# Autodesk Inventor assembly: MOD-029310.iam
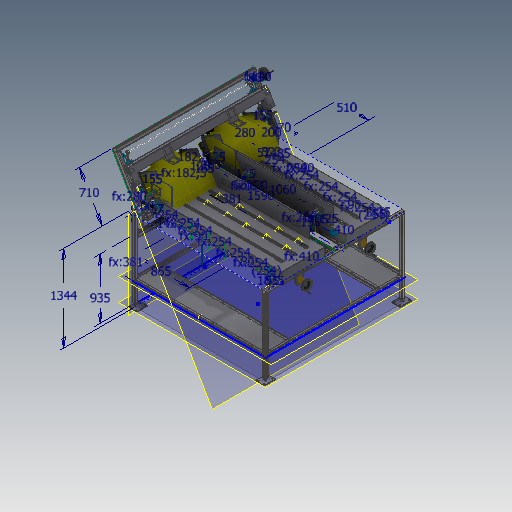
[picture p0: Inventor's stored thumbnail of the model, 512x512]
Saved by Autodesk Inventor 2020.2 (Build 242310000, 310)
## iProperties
Created: 2019-10
Part Number: MOD-029310.iam
Document SubType Name: Assembly
Designer: lutzd
Mass: 576257 g
Surface Area: 445992 cm^2
Volume: 104131 cm^3
Density: 5.53397 g/cm^3
VLDS_Profile: Default Assembly
VLDS_TimeStamp: 2016-07-29
VLDS_FailCnt: 0
VLDS_AcceptCnt: 0
Dimensions: 2423,5x1993,9x2729,7 mm
Mass: 576,257 kg
DocNumber: MOD-029310.iam
Folder: 01 - Themengebiete\Simplification\01 - Packaging machine\.\
VDS_Category: 3D Komponenten
VDS_NumSchm: Kein
Title: MOD-029310
Author: lutzd
Revision Number: -
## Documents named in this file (17)
- D:\07 - DEMODATEN\OTX 2019 - Dataset - UPDATE - Dez2019\Designs\07-Packing machine\MOD-029310.iam
- D:\07 - DEMODATEN\OTX 2019 - Dataset - UPDATE - Dez2019\Designs\07-Packing machine\500586R.iam
- D:\07 - DEMODATEN\OTX 2019 - Dataset - UPDATE - Dez2019\Designs\07-Packing machine\Parts\ADSK-011671.ipt
- D:\07 - DEMODATEN\OTX 2019 - Dataset - UPDATE - Dez2019\Designs\07-Packing machine\ADSK-014389.iam
- D:\07 - DEMODATEN\OTX 2019 - Dataset - UPDATE - Dez2019\Content Center Files\de-DE\DIN 125-1  B\DIN 125-1 - B 8,4.ipt
- D:\07 - DEMODATEN\OTX 2019 - Dataset - UPDATE - Dez2019\Content Center Files\de-DE\ISO 4762(2)\ISO 4762 - M8 x 25ISO.ipt
- D:\07 - DEMODATEN\OTX 2019 - Dataset - UPDATE - Dez2019\Designs\07-Packing machine\SUB-229310.iam
- D:\07 - DEMODATEN\OTX 2019 - Dataset - UPDATE - Dez2019\Content Center Files\de-DE\ISO 4762(2)\ISO 4762 - M8 x 16ISO.ipt
- D:\07 - DEMODATEN\OTX 2019 - Dataset - UPDATE - Dez2019\Designs\07-Packing machine\SUB-239310.iam
- D:\07 - DEMODATEN\OTX 2019 - Dataset - UPDATE - Dez2019\Designs\07-Packing machine\SUB-279310.iam
- D:\07 - DEMODATEN\OTX 2019 - Dataset - UPDATE - Dez2019\Content Center Files\de-DE\ISO 4762(2)\ISO 4762 - M8 x 20ISO.ipt
- D:\07 - DEMODATEN\OTX 2019 - Dataset - UPDATE - Dez2019\Designs\07-Packing machine\SUB-299310.iam
- D:\07 - DEMODATEN\OTX 2019 - Dataset - UPDATE - Dez2019\Designs\07-Packing machine\SUB-269310.iam
- D:\07 - DEMODATEN\OTX 2019 - Dataset - UPDATE - Dez2019\Designs\07-Packing machine\500652R.iam
- D:\07 - DEMODATEN\OTX 2019 - Dataset - UPDATE - Dez2019\Designs\07-Packing machine\500652L.iam
- D:\07 - DEMODATEN\OTX 2019 - Dataset - UPDATE - Dez2019\Designs\07-Packing machine\SUB-259310.iam
- D:\07 - DEMODATEN\OTX 2019 - Dataset - UPDATE - Dez2019\Designs\07-Packing machine\Parts\ADSK-014502.ipt
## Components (534 placed, 16 different names)
1. 500586R:1 [sub-assembly] — Passend:49, Fluchtend:4, Passend:58, Passend:59, Fluchtend:5, Fluchtend:6, Fluchtend:7, Passend:60, Passend:141, Passend:143, Fluchtend:8, Fluchtend:9, Passend:161, Passend:174, Fluchtend:10, Passend:272, Passend:289, Passend:290, Passend:295, Fluchtend:293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
2. ADSK-011671:1
3. ADSK-011671:2
4. ADSK-014389:1 [sub-assembly] — Passend:48, Passend:49, Fluchtend:4, Passend:51, Passend:53, Passend:55, Passend:57, Passend:391, Fluchtend:393
5. SUB-229310:1 [sub-assembly] — Passend:58, Fluchtend:5, Fluchtend:7, Passend:145, Passend:147, Passend:149, Passend:151
6. SUB-229310:2 [sub-assembly] — Passend:59, Fluchtend:6, Passend:60, Passend:62, Passend:64, Passend:66, Passend:68, Passend:70, Passend:72, Passend:74, Passend:76, Passend:78, Passend:80, Passend:82, Passend:84, Passend:86, Passend:88, Passend:90, Passend:92, Passend:110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
7. SUB-239310:1 [sub-assembly] — Passend:141, Passend:143, Fluchtend:8, Passend:169, Passend:171, Passend:173, Passend:176, Passend:178, Passend:180, Passend:182, Passend:184, Passend:186, Passend:188, Passend:190, Passend:240, Passend:242, Passend:260, Passend:262, Fluchtend:298, Passend:385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
8. SUB-279310:1 [sub-assembly] — Fluchtend:9, Passend:161, Passend:163, Passend:165, Passend:167, Passend:174, Passend:192, Passend:194, Passend:196, Passend:198, Passend:200, Passend:202, Passend:204, Passend:206, Passend:244, Passend:246, Passend:256, Passend:258, Passend:271, Fluchtend:389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
9. SUB-299310:1 [sub-assembly] — Passend:271, Fluchtend:10, Passend:272, Passend:274, Passend:276, Passend:278, Passend:280, Passend:282, Passend:284
10. SUB-269310:1 [sub-assembly] — Passend:289, Fluchtend:292, Passend:290, Passend:292, Passend:294, Passend:296, Passend:299
11. 500652R:1 [sub-assembly] — Passend:295, Fluchtend:293, Passend:296, Fluchtend:390
12. 500652L:1 [sub-assembly] — Passend:297, Passend:298, Passend:299, Fluchtend:299
13. SUB-259310:1 [sub-assembly] — Fluchtend:294, Passend:390, Fluchtend:295, Fluchtend:391, Passend:301, Passend:303, Passend:305, Passend:307, Passend:309, Passend:311, Passend:313, Passend:315, Passend:317, Passend:319, Passend:321, Passend:323, Passend:325, Passend:327, Passend:329, Passend:331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
14. ADSK-014502:307 — Fluchtend:392, Passend:391, Fluchtend:393
15. DIN 125-1 B B 8,4:85 — Passend:377, Passend:379
16. DIN 125-1 B B 8,4:86
17. DIN 125-1 B B 8,4:87
18. DIN 125-1 B B 8,4:88
19. DIN 125-1 B B 8,4:89 — Passend:301, Passend:361, Passend:363, Passend:365, Passend:367
20. DIN 125-1 B B 8,4:90 — Passend:303
21. DIN 125-1 B B 8,4:91 — Passend:305
22. DIN 125-1 B B 8,4:92 — Passend:307
23. DIN 125-1 B B 8,4:93 — Passend:309, Passend:369, Passend:371, Passend:373, Passend:375
24. DIN 125-1 B B 8,4:94 — Passend:311
25. DIN 125-1 B B 8,4:95 — Passend:313
26. DIN 125-1 B B 8,4:96 — Passend:315
27. DIN 125-1 B B 8,4:97
28. DIN 125-1 B B 8,4:98
29. DIN 125-1 B B 8,4:99 — Passend:317
30. DIN 125-1 B B 8,4:100 — Passend:319, Passend:353, Passend:355, Passend:357, Passend:359
31. DIN 125-1 B B 8,4:101 — Passend:321
32. DIN 125-1 B B 8,4:102 — Passend:323
33. DIN 125-1 B B 8,4:103 — Passend:325
34. DIN 125-1 B B 8,4:104 — Passend:327
35. DIN 125-1 B B 8,4:105 — Passend:329
36. DIN 125-1 B B 8,4:106 — Passend:331
37. DIN 125-1 B B 8,4:107 — Passend:333
38. DIN 125-1 B B 8,4:108 — Passend:335
39. DIN 125-1 B B 8,4:109 — Passend:337
40. DIN 125-1 B B 8,4:110 — Passend:339, Passend:341, Passend:343, Passend:345, Passend:351
41. ISO 4762 M8 x 20:11 — Passend:341
42. ISO 4762 M8 x 20:12 — Passend:343
43. ISO 4762 M8 x 20:13 — Passend:345
44. ISO 4762 M8 x 20:16 — Passend:351
45. ISO 4762 M8 x 25:29
46. ISO 4762 M8 x 25:30
47. ISO 4762 M8 x 20:17 — Passend:353
48. ISO 4762 M8 x 20:18 — Passend:355
49. ISO 4762 M8 x 20:19 — Passend:357
50. ISO 4762 M8 x 20:20 — Passend:359
51. ISO 4762 M8 x 25:31
52. ISO 4762 M8 x 25:32
53. ISO 4762 M8 x 20:21 — Passend:361
54. ISO 4762 M8 x 20:22 — Passend:363
55. ISO 4762 M8 x 20:23 — Passend:365
56. ISO 4762 M8 x 20:24 — Passend:367
57. ISO 4762 M8 x 16:51 — Passend:369
58. ISO 4762 M8 x 16:52 — Passend:371
59. ISO 4762 M8 x 16:53 — Passend:373
60. ISO 4762 M8 x 16:54 — Passend:375
61. ISO 4762 M8 x 16:55 — Passend:377
62. ISO 4762 M8 x 16:56 — Passend:379
63. DIN 125-1 B B 8,4:69
64. DIN 125-1 B B 8,4:70
65. DIN 125-1 B B 8,4:71
66. DIN 125-1 B B 8,4:72
67. DIN 125-1 B B 8,4:73
68. DIN 125-1 B B 8,4:74
69. DIN 125-1 B B 8,4:75 — Passend:292
70. DIN 125-1 B B 8,4:76 — Passend:294
71. DIN 125-1 B B 8,4:77
72. DIN 125-1 B B 8,4:78
73. DIN 125-1 B B 8,4:79
74. DIN 125-1 B B 8,4:80
75. DIN 125-1 B B 8,4:81
76. DIN 125-1 B B 8,4:82
77. DIN 125-1 B B 8,4:83
78. DIN 125-1 B B 8,4:84
79. ISO 4762 M8 x 25:13
80. ISO 4762 M8 x 25:14
81. ISO 4762 M8 x 25:15
82. ISO 4762 M8 x 25:16
83. ISO 4762 M8 x 25:17
84. ISO 4762 M8 x 25:18
85. ISO 4762 M8 x 25:19
86. ISO 4762 M8 x 25:20
87. ISO 4762 M8 x 25:21
88. ISO 4762 M8 x 25:22
89. ISO 4762 M8 x 25:23
90. ISO 4762 M8 x 25:24
91. ISO 4762 M8 x 25:25
92. ISO 4762 M8 x 25:26
93. ISO 4762 M8 x 25:27
94. ISO 4762 M8 x 25:28
95. DIN 125-1 B B 8,4:63 — Passend:274
96. DIN 125-1 B B 8,4:64 — Passend:276
97. DIN 125-1 B B 8,4:65 — Passend:278
98. DIN 125-1 B B 8,4:66 — Passend:280
99. DIN 125-1 B B 8,4:67 — Passend:282, Passend:286, Passend:288
100. DIN 125-1 B B 8,4:68 — Passend:284
101. ISO 4762 M8 x 20:5 — Passend:286
102. ISO 4762 M8 x 20:6 — Passend:288
103. ISO 4762 M8 x 20:7
104. ISO 4762 M8 x 20:8
105. ISO 4762 M8 x 20:9
106. ISO 4762 M8 x 20:10
107. DIN 125-1 B B 8,4:59 — Passend:256
108. DIN 125-1 B B 8,4:60 — Passend:258, Passend:268, Passend:270
109. DIN 125-1 B B 8,4:61 — Passend:260, Passend:264, Passend:266
110. DIN 125-1 B B 8,4:62 — Passend:262
111. ISO 4762 M8 x 16:47 — Passend:264
112. ISO 4762 M8 x 16:48 — Passend:266
113. ISO 4762 M8 x 16:49 — Passend:268
114. ISO 4762 M8 x 16:50 — Passend:270
115. DIN 125-1 B B 8,4:55 — Passend:240
116. DIN 125-1 B B 8,4:56 — Passend:242, Passend:252, Passend:254
117. DIN 125-1 B B 8,4:57 — Passend:244, Passend:248, Passend:250
118. DIN 125-1 B B 8,4:58 — Passend:246
119. ISO 4762 M8 x 20:1 — Passend:248
120. ISO 4762 M8 x 20:2 — Passend:250
121. ISO 4762 M8 x 20:3 — Passend:252
122. ISO 4762 M8 x 20:4 — Passend:254
123. DIN 125-1 B B 8,4:33 — Passend:163
124. DIN 125-1 B B 8,4:34 — Passend:165
125. DIN 125-1 B B 8,4:35 — Passend:167
126. DIN 125-1 B B 8,4:36 — Passend:169
127. DIN 125-1 B B 8,4:37 — Passend:171
128. DIN 125-1 B B 8,4:38 — Passend:173
129. ISO 4762 M8 x 16:25
130. ISO 4762 M8 x 16:26
131. ISO 4762 M8 x 16:27
132. ISO 4762 M8 x 16:28
133. ISO 4762 M8 x 16:29
134. ISO 4762 M8 x 16:30
135. DIN 125-1 B B 8,4:39 — Passend:176
136. DIN 125-1 B B 8,4:40 — Passend:178
137. DIN 125-1 B B 8,4:41 — Passend:180
138. DIN 125-1 B B 8,4:42 — Passend:182
139. DIN 125-1 B B 8,4:43 — Passend:184, Passend:208, Passend:210, Passend:212, Passend:214, Passend:216, Passend:218, Passend:220, Passend:222
140. DIN 125-1 B B 8,4:44 — Passend:186
141. DIN 125-1 B B 8,4:45 — Passend:188
142. DIN 125-1 B B 8,4:46 — Passend:190
143. DIN 125-1 B B 8,4:47 — Passend:192, Passend:224, Passend:226, Passend:228, Passend:230, Passend:232, Passend:234, Passend:236, Passend:238
144. DIN 125-1 B B 8,4:48 — Passend:194
145. DIN 125-1 B B 8,4:49 — Passend:196
146. DIN 125-1 B B 8,4:50 — Passend:198
147. DIN 125-1 B B 8,4:51 — Passend:200
148. DIN 125-1 B B 8,4:52 — Passend:202
149. DIN 125-1 B B 8,4:53 — Passend:204
150. DIN 125-1 B B 8,4:54 — Passend:206
151. ISO 4762 M8 x 16:31 — Passend:208
152. ISO 4762 M8 x 16:32 — Passend:210
153. ISO 4762 M8 x 16:33 — Passend:212
154. ISO 4762 M8 x 16:34 — Passend:214
155. ISO 4762 M8 x 16:35 — Passend:216
156. ISO 4762 M8 x 16:36 — Passend:218
157. ISO 4762 M8 x 16:37 — Passend:220
158. ISO 4762 M8 x 16:38 — Passend:222
159. ISO 4762 M8 x 16:39 — Passend:224
160. ISO 4762 M8 x 16:40 — Passend:226
161. ISO 4762 M8 x 16:41 — Passend:228
162. ISO 4762 M8 x 16:42 — Passend:230
163. ISO 4762 M8 x 16:43 — Passend:232
164. ISO 4762 M8 x 16:44 — Passend:234
165. ISO 4762 M8 x 16:45 — Passend:236
166. ISO 4762 M8 x 16:46 — Passend:238
167. DIN 125-1 B B 8,4:29 — Passend:145, Passend:153, Passend:155, Passend:157, Passend:159
168. DIN 125-1 B B 8,4:30 — Passend:147
169. DIN 125-1 B B 8,4:31 — Passend:149
170. DIN 125-1 B B 8,4:32 — Passend:151
171. ISO 4762 M8 x 16:21 — Passend:153
172. ISO 4762 M8 x 16:22 — Passend:155
173. ISO 4762 M8 x 16:23 — Passend:157
174. ISO 4762 M8 x 16:24 — Passend:159
175. ISO 4762 M8 x 16:17 — Passend:134
176. ISO 4762 M8 x 16:18 — Passend:136
177. ISO 4762 M8 x 16:19 — Passend:138
178. ISO 4762 M8 x 16:20 — Passend:140
179. ISO 4762 M8 x 16:6 — Passend:112
180. ISO 4762 M8 x 16:7 — Passend:114
181. ISO 4762 M8 x 16:8 — Passend:116
182. ISO 4762 M8 x 16:9 — Passend:118
183. ISO 4762 M8 x 16:10 — Passend:120
184. ISO 4762 M8 x 16:11 — Passend:122
185. ISO 4762 M8 x 16:12 — Passend:124
186. ISO 4762 M8 x 16:13 — Passend:126
187. ISO 4762 M8 x 16:14 — Passend:128
188. ISO 4762 M8 x 16:15 — Passend:130
189. ISO 4762 M8 x 16:16 — Passend:132
190. DIN 125-1 B B 8,4:20 — Passend:76
191. DIN 125-1 B B 8,4:21 — Passend:78
192. DIN 125-1 B B 8,4:22 — Passend:80
193. DIN 125-1 B B 8,4:23 — Passend:82
194. DIN 125-1 B B 8,4:24 — Passend:84
195. DIN 125-1 B B 8,4:25 — Passend:86
196. DIN 125-1 B B 8,4:26 — Passend:88
197. DIN 125-1 B B 8,4:27 — Passend:90
198. DIN 125-1 B B 8,4:28 — Passend:92
199. ISO 4762 M8 x 16:5 — Passend:110
200. DIN 125-1 B B 8,4:13 — Passend:62
201. DIN 125-1 B B 8,4:14 — Passend:64
202. DIN 125-1 B B 8,4:15 — Passend:66
203. DIN 125-1 B B 8,4:16 — Passend:68
204. DIN 125-1 B B 8,4:17 — Passend:70
205. DIN 125-1 B B 8,4:18 — Passend:72
206. DIN 125-1 B B 8,4:19 — Passend:74
207. DIN 125-1 B B 8,4:1 — Passend:51
208. DIN 125-1 B B 8,4:2 — Passend:53
209. DIN 125-1 B B 8,4:3 — Passend:55
210. DIN 125-1 B B 8,4:4 — Passend:57
211. DIN 125-1 B B 8,4:5
212. DIN 125-1 B B 8,4:6
213. DIN 125-1 B B 8,4:7
214. DIN 125-1 B B 8,4:8
215. DIN 125-1 B B 8,4:9
216. DIN 125-1 B B 8,4:10
217. DIN 125-1 B B 8,4:11
218. DIN 125-1 B B 8,4:12
219. ISO 4762 M8 x 25:1
220. ISO 4762 M8 x 25:2
221. ISO 4762 M8 x 25:3
222. ISO 4762 M8 x 25:4
223. ISO 4762 M8 x 25:5
224. ISO 4762 M8 x 25:6
225. ISO 4762 M8 x 25:7
226. ISO 4762 M8 x 25:8
227. ISO 4762 M8 x 25:9
228. ISO 4762 M8 x 25:10
229. ISO 4762 M8 x 25:11
230. ISO 4762 M8 x 25:12
231. ADSK-014502:1 [sub-assembly] — Fluchtend:389, Passend:381, Fluchtend:390
232. ADSK-014502:153 [sub-assembly] — Fluchtend:298, Fluchtend:299, Passend:385
233. ADSK-014502:305
234. ADSK-014502:306
235. ADSK-014502:3 [sub-assembly]
236. ADSK-014502:155 [sub-assembly]
237. ADSK-014502:4 [sub-assembly]
238. ADSK-014502:156 [sub-assembly]
239. ADSK-014502:5 [sub-assembly]
240. ADSK-014502:157 [sub-assembly]
241. ADSK-014502:6 [sub-assembly]
242. ADSK-014502:158 [sub-assembly]
243. ADSK-014502:7 [sub-assembly]
244. ADSK-014502:159 [sub-assembly]
245. ADSK-014502:8 [sub-assembly]
246. ADSK-014502:160 [sub-assembly]
247. ADSK-014502:9 [sub-assembly]
248. ADSK-014502:161 [sub-assembly]
249. ADSK-014502:10 [sub-assembly]
250. ADSK-014502:162 [sub-assembly]
251. ADSK-014502:11 [sub-assembly]
252. ADSK-014502:163 [sub-assembly]
253. ADSK-014502:12 [sub-assembly]
254. ADSK-014502:164 [sub-assembly]
255. ADSK-014502:13 [sub-assembly]
256. ADSK-014502:165 [sub-assembly]
257. ADSK-014502:14 [sub-assembly]
258. ADSK-014502:166 [sub-assembly]
259. ADSK-014502:15 [sub-assembly]
260. ADSK-014502:167 [sub-assembly]
261. ADSK-014502:16 [sub-assembly]
262. ADSK-014502:168 [sub-assembly]
263. ADSK-014502:17 [sub-assembly]
264. ADSK-014502:169 [sub-assembly]
265. ADSK-014502:18 [sub-assembly]
266. ADSK-014502:170 [sub-assembly]
267. ADSK-014502:19 [sub-assembly]
268. ADSK-014502:171 [sub-assembly]
269. ADSK-014502:20 [sub-assembly]
270. ADSK-014502:172 [sub-assembly]
271. ADSK-014502:21 [sub-assembly]
272. ADSK-014502:173 [sub-assembly]
273. ADSK-014502:22 [sub-assembly]
274. ADSK-014502:174 [sub-assembly]
275. ADSK-014502:23 [sub-assembly]
276. ADSK-014502:175 [sub-assembly]
277. ADSK-014502:24 [sub-assembly]
278. ADSK-014502:176 [sub-assembly]
279. ADSK-014502:25 [sub-assembly]
280. ADSK-014502:177 [sub-assembly]
281. ADSK-014502:26 [sub-assembly]
282. ADSK-014502:178 [sub-assembly]
283. ADSK-014502:27 [sub-assembly]
284. ADSK-014502:179 [sub-assembly]
285. ADSK-014502:28 [sub-assembly]
286. ADSK-014502:180 [sub-assembly]
287. ADSK-014502:29 [sub-assembly]
288. ADSK-014502:181 [sub-assembly]
289. ADSK-014502:30 [sub-assembly]
290. ADSK-014502:182 [sub-assembly]
291. ADSK-014502:31 [sub-assembly]
292. ADSK-014502:183 [sub-assembly]
293. ADSK-014502:32 [sub-assembly]
294. ADSK-014502:184 [sub-assembly]
295. ADSK-014502:33 [sub-assembly]
296. ADSK-014502:185 [sub-assembly]
297. ADSK-014502:34 [sub-assembly]
298. ADSK-014502:186 [sub-assembly]
299. ADSK-014502:35 [sub-assembly]
300. ADSK-014502:187 [sub-assembly]
301. ADSK-014502:36 [sub-assembly]
302. ADSK-014502:188 [sub-assembly]
303. ADSK-014502:37 [sub-assembly]
304. ADSK-014502:189 [sub-assembly]
305. ADSK-014502:38 [sub-assembly]
306. ADSK-014502:190 [sub-assembly]
307. ADSK-014502:39 [sub-assembly]
308. ADSK-014502:191 [sub-assembly]
309. ADSK-014502:40 [sub-assembly]
310. ADSK-014502:192 [sub-assembly]
311. ADSK-014502:41 [sub-assembly]
312. ADSK-014502:193 [sub-assembly]
313. ADSK-014502:42 [sub-assembly]
314. ADSK-014502:194 [sub-assembly]
315. ADSK-014502:43 [sub-assembly]
316. ADSK-014502:195 [sub-assembly]
317. ADSK-014502:44 [sub-assembly]
318. ADSK-014502:196 [sub-assembly]
319. ADSK-014502:45 [sub-assembly]
320. ADSK-014502:197 [sub-assembly]
321. ADSK-014502:46 [sub-assembly]
322. ADSK-014502:198 [sub-assembly]
323. ADSK-014502:47 [sub-assembly]
324. ADSK-014502:199 [sub-assembly]
325. ADSK-014502:48 [sub-assembly]
326. ADSK-014502:200 [sub-assembly]
327. ADSK-014502:49 [sub-assembly]
328. ADSK-014502:201 [sub-assembly]
329. ADSK-014502:50 [sub-assembly]
330. ADSK-014502:202 [sub-assembly]
331. ADSK-014502:51 [sub-assembly]
332. ADSK-014502:203 [sub-assembly]
333. ADSK-014502:52 [sub-assembly] — Passend:384
334. ADSK-014502:204 [sub-assembly] — Passend:386, Passend:389
335. ADSK-014502:53 [sub-assembly] — Passend:382, Passend:383, Passend:384
336. ADSK-014502:205 [sub-assembly] — Passend:386, Fluchtend:388, Passend:387, Passend:388, Passend:389
337. ADSK-014502:54 [sub-assembly]
338. ADSK-014502:206 [sub-assembly]
339. ADSK-014502:55 [sub-assembly]
340. ADSK-014502:207 [sub-assembly]
341. ADSK-014502:56 [sub-assembly]
342. ADSK-014502:208 [sub-assembly]
343. ADSK-014502:57 [sub-assembly]
344. ADSK-014502:209 [sub-assembly]
345. ADSK-014502:58 [sub-assembly]
346. ADSK-014502:210 [sub-assembly]
347. ADSK-014502:59 [sub-assembly]
348. ADSK-014502:211 [sub-assembly]
349. ADSK-014502:60 [sub-assembly]
350. ADSK-014502:212 [sub-assembly]
351. ADSK-014502:61 [sub-assembly]
352. ADSK-014502:213 [sub-assembly]
353. ADSK-014502:62 [sub-assembly]
354. ADSK-014502:214 [sub-assembly]
355. ADSK-014502:63 [sub-assembly]
356. ADSK-014502:215 [sub-assembly]
357. ADSK-014502:64 [sub-assembly]
358. ADSK-014502:216 [sub-assembly]
359. ADSK-014502:65 [sub-assembly]
360. ADSK-014502:217 [sub-assembly]
361. ADSK-014502:66 [sub-assembly]
362. ADSK-014502:218 [sub-assembly]
363. ADSK-014502:67 [sub-assembly]
364. ADSK-014502:219 [sub-assembly]
365. ADSK-014502:68 [sub-assembly]
366. ADSK-014502:220 [sub-assembly]
367. ADSK-014502:69 [sub-assembly]
368. ADSK-014502:221 [sub-assembly]
369. ADSK-014502:70 [sub-assembly]
370. ADSK-014502:222 [sub-assembly]
371. ADSK-014502:71 [sub-assembly]
372. ADSK-014502:223 [sub-assembly]
373. ADSK-014502:72 [sub-assembly]
374. ADSK-014502:224 [sub-assembly]
375. ADSK-014502:73 [sub-assembly]
376. ADSK-014502:225 [sub-assembly]
377. ADSK-014502:74 [sub-assembly]
378. ADSK-014502:226 [sub-assembly]
379. ADSK-014502:75 [sub-assembly]
380. ADSK-014502:227 [sub-assembly]
381. ADSK-014502:76 [sub-assembly]
382. ADSK-014502:228 [sub-assembly]
383. ADSK-014502:77 [sub-assembly]
384. ADSK-014502:229 [sub-assembly]
385. ADSK-014502:78 [sub-assembly]
386. ADSK-014502:230 [sub-assembly]
387. ADSK-014502:79 [sub-assembly]
388. ADSK-014502:231 [sub-assembly]
389. ADSK-014502:80 [sub-assembly]
390. ADSK-014502:232 [sub-assembly]
391. ADSK-014502:81 [sub-assembly]
392. ADSK-014502:233 [sub-assembly]
393. ADSK-014502:82 [sub-assembly]
394. ADSK-014502:234 [sub-assembly]
395. ADSK-014502:83 [sub-assembly]
396. ADSK-014502:235 [sub-assembly]
397. ADSK-014502:84 [sub-assembly]
398. ADSK-014502:236 [sub-assembly]
399. ADSK-014502:85 [sub-assembly]
400. ADSK-014502:237 [sub-assembly]
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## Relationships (194: Mate 175, Flush 19)
- Passend:48 [Mate]: ADSK-014389:1
- Passend:49 [Mate]: 500586R:1 ↔ ADSK-014389:1
- Fluchtend:4 [Flush]: 500586R:1 ↔ ADSK-014389:1
- Passend:51 [Mate]: ADSK-014389:1 ↔ DIN 125-1 B B 8,4:1
- Passend:53 [Mate]: ADSK-014389:1 ↔ DIN 125-1 B B 8,4:2
- Passend:55 [Mate]: ADSK-014389:1 ↔ DIN 125-1 B B 8,4:3
- Passend:57 [Mate]: ADSK-014389:1 ↔ DIN 125-1 B B 8,4:4
- Passend:58 [Mate]: 500586R:1 ↔ SUB-229310:1
- Passend:59 [Mate]: 500586R:1 ↔ SUB-229310:2
- Fluchtend:5 [Flush]: 500586R:1 ↔ SUB-229310:1
- Fluchtend:6 [Flush]: 500586R:1 ↔ SUB-229310:2
- Fluchtend:7 [Flush]: 500586R:1 ↔ SUB-229310:1
- Passend:60 [Mate]: 500586R:1 ↔ SUB-229310:2
- Passend:62 [Mate]: SUB-229310:2 ↔ DIN 125-1 B B 8,4:13
- Passend:64 [Mate]: SUB-229310:2 ↔ DIN 125-1 B B 8,4:14
- Passend:66 [Mate]: SUB-229310:2 ↔ DIN 125-1 B B 8,4:15
- Passend:68 [Mate]: SUB-229310:2 ↔ DIN 125-1 B B 8,4:16
- Passend:70 [Mate]: SUB-229310:2 ↔ DIN 125-1 B B 8,4:17
- Passend:72 [Mate]: SUB-229310:2 ↔ DIN 125-1 B B 8,4:18
- Passend:74 [Mate]: SUB-229310:2 ↔ DIN 125-1 B B 8,4:19
- Passend:76 [Mate]: SUB-229310:2 ↔ DIN 125-1 B B 8,4:20
- Passend:78 [Mate]: SUB-229310:2 ↔ DIN 125-1 B B 8,4:21
- Passend:80 [Mate]: SUB-229310:2 ↔ DIN 125-1 B B 8,4:22
- Passend:82 [Mate]: SUB-229310:2 ↔ DIN 125-1 B B 8,4:23
- Passend:84 [Mate]: SUB-229310:2 ↔ DIN 125-1 B B 8,4:24
- Passend:86 [Mate]: SUB-229310:2 ↔ DIN 125-1 B B 8,4:25
- Passend:88 [Mate]: SUB-229310:2 ↔ DIN 125-1 B B 8,4:26
- Passend:90 [Mate]: SUB-229310:2 ↔ DIN 125-1 B B 8,4:27
- Passend:92 [Mate]: SUB-229310:2 ↔ DIN 125-1 B B 8,4:28
- Passend:110 [Mate]: SUB-229310:2 ↔ ISO 4762 M8 x 16:5
- Passend:112 [Mate]: SUB-229310:2 ↔ ISO 4762 M8 x 16:6
- Passend:114 [Mate]: SUB-229310:2 ↔ ISO 4762 M8 x 16:7
- Passend:116 [Mate]: SUB-229310:2 ↔ ISO 4762 M8 x 16:8
- Passend:118 [Mate]: SUB-229310:2 ↔ ISO 4762 M8 x 16:9
- Passend:120 [Mate]: SUB-229310:2 ↔ ISO 4762 M8 x 16:10
- Passend:122 [Mate]: SUB-229310:2 ↔ ISO 4762 M8 x 16:11
- Passend:124 [Mate]: SUB-229310:2 ↔ ISO 4762 M8 x 16:12
- Passend:126 [Mate]: SUB-229310:2 ↔ ISO 4762 M8 x 16:13
- Passend:128 [Mate]: SUB-229310:2 ↔ ISO 4762 M8 x 16:14
- Passend:130 [Mate]: SUB-229310:2 ↔ ISO 4762 M8 x 16:15
- Passend:132 [Mate]: SUB-229310:2 ↔ ISO 4762 M8 x 16:16
- Passend:134 [Mate]: SUB-229310:2 ↔ ISO 4762 M8 x 16:17
- Passend:136 [Mate]: SUB-229310:2 ↔ ISO 4762 M8 x 16:18
- Passend:138 [Mate]: SUB-229310:2 ↔ ISO 4762 M8 x 16:19
- Passend:140 [Mate]: SUB-229310:2 ↔ ISO 4762 M8 x 16:20
- Passend:141 [Mate]: 500586R:1 ↔ SUB-239310:1
- Passend:143 [Mate]: 500586R:1 ↔ SUB-239310:1
- Fluchtend:8 [Flush]: 500586R:1 ↔ SUB-239310:1
- Passend:145 [Mate]: SUB-229310:1 ↔ DIN 125-1 B B 8,4:29
- Passend:147 [Mate]: SUB-229310:1 ↔ DIN 125-1 B B 8,4:30
- Passend:149 [Mate]: SUB-229310:1 ↔ DIN 125-1 B B 8,4:31
- Passend:151 [Mate]: SUB-229310:1 ↔ DIN 125-1 B B 8,4:32
- Passend:153 [Mate]: DIN 125-1 B B 8,4:29 ↔ ISO 4762 M8 x 16:21
- Passend:155 [Mate]: DIN 125-1 B B 8,4:29 ↔ ISO 4762 M8 x 16:22
- Passend:157 [Mate]: DIN 125-1 B B 8,4:29 ↔ ISO 4762 M8 x 16:23
- Passend:159 [Mate]: DIN 125-1 B B 8,4:29 ↔ ISO 4762 M8 x 16:24
- Fluchtend:9 [Flush]: 500586R:1 ↔ SUB-279310:1
- Passend:161 [Mate]: 500586R:1 ↔ SUB-279310:1
- Passend:163 [Mate]: SUB-279310:1 ↔ DIN 125-1 B B 8,4:33
- Passend:165 [Mate]: SUB-279310:1 ↔ DIN 125-1 B B 8,4:34
- Passend:167 [Mate]: SUB-279310:1 ↔ DIN 125-1 B B 8,4:35
- Passend:169 [Mate]: SUB-239310:1 ↔ DIN 125-1 B B 8,4:36
- Passend:171 [Mate]: SUB-239310:1 ↔ DIN 125-1 B B 8,4:37
- Passend:173 [Mate]: SUB-239310:1 ↔ DIN 125-1 B B 8,4:38
- Passend:174 [Mate]: 500586R:1 ↔ SUB-279310:1
- Passend:176 [Mate]: SUB-239310:1 ↔ DIN 125-1 B B 8,4:39
- Passend:178 [Mate]: SUB-239310:1 ↔ DIN 125-1 B B 8,4:40
- Passend:180 [Mate]: SUB-239310:1 ↔ DIN 125-1 B B 8,4:41
- Passend:182 [Mate]: SUB-239310:1 ↔ DIN 125-1 B B 8,4:42
- Passend:184 [Mate]: SUB-239310:1 ↔ DIN 125-1 B B 8,4:43
- Passend:186 [Mate]: SUB-239310:1 ↔ DIN 125-1 B B 8,4:44
- Passend:188 [Mate]: SUB-239310:1 ↔ DIN 125-1 B B 8,4:45
- Passend:190 [Mate]: SUB-239310:1 ↔ DIN 125-1 B B 8,4:46
- Passend:192 [Mate]: SUB-279310:1 ↔ DIN 125-1 B B 8,4:47
- Passend:194 [Mate]: SUB-279310:1 ↔ DIN 125-1 B B 8,4:48
- Passend:196 [Mate]: SUB-279310:1 ↔ DIN 125-1 B B 8,4:49
- Passend:198 [Mate]: SUB-279310:1 ↔ DIN 125-1 B B 8,4:50
- Passend:200 [Mate]: SUB-279310:1 ↔ DIN 125-1 B B 8,4:51
- Passend:202 [Mate]: SUB-279310:1 ↔ DIN 125-1 B B 8,4:52
- Passend:204 [Mate]: SUB-279310:1 ↔ DIN 125-1 B B 8,4:53
- Passend:206 [Mate]: SUB-279310:1 ↔ DIN 125-1 B B 8,4:54
- Passend:208 [Mate]: DIN 125-1 B B 8,4:43 ↔ ISO 4762 M8 x 16:31
- Passend:210 [Mate]: DIN 125-1 B B 8,4:43 ↔ ISO 4762 M8 x 16:32
- Passend:212 [Mate]: DIN 125-1 B B 8,4:43 ↔ ISO 4762 M8 x 16:33
- Passend:214 [Mate]: DIN 125-1 B B 8,4:43 ↔ ISO 4762 M8 x 16:34
- Passend:216 [Mate]: DIN 125-1 B B 8,4:43 ↔ ISO 4762 M8 x 16:35
- Passend:218 [Mate]: DIN 125-1 B B 8,4:43 ↔ ISO 4762 M8 x 16:36
- Passend:220 [Mate]: DIN 125-1 B B 8,4:43 ↔ ISO 4762 M8 x 16:37
- Passend:222 [Mate]: DIN 125-1 B B 8,4:43 ↔ ISO 4762 M8 x 16:38
- Passend:224 [Mate]: DIN 125-1 B B 8,4:47 ↔ ISO 4762 M8 x 16:39
- Passend:226 [Mate]: DIN 125-1 B B 8,4:47 ↔ ISO 4762 M8 x 16:40
- Passend:228 [Mate]: DIN 125-1 B B 8,4:47 ↔ ISO 4762 M8 x 16:41
- Passend:230 [Mate]: DIN 125-1 B B 8,4:47 ↔ ISO 4762 M8 x 16:42
- Passend:232 [Mate]: DIN 125-1 B B 8,4:47 ↔ ISO 4762 M8 x 16:43
- Passend:234 [Mate]: DIN 125-1 B B 8,4:47 ↔ ISO 4762 M8 x 16:44
- Passend:236 [Mate]: DIN 125-1 B B 8,4:47 ↔ ISO 4762 M8 x 16:45
- Passend:238 [Mate]: DIN 125-1 B B 8,4:47 ↔ ISO 4762 M8 x 16:46
- Passend:240 [Mate]: SUB-239310:1 ↔ DIN 125-1 B B 8,4:55
- Passend:242 [Mate]: SUB-239310:1 ↔ DIN 125-1 B B 8,4:56
- Passend:244 [Mate]: SUB-279310:1 ↔ DIN 125-1 B B 8,4:57
- Passend:246 [Mate]: SUB-279310:1 ↔ DIN 125-1 B B 8,4:58
- Passend:248 [Mate]: DIN 125-1 B B 8,4:57 ↔ ISO 4762 M8 x 20:1
- Passend:250 [Mate]: DIN 125-1 B B 8,4:57 ↔ ISO 4762 M8 x 20:2
- Passend:252 [Mate]: DIN 125-1 B B 8,4:56 ↔ ISO 4762 M8 x 20:3
- Passend:254 [Mate]: DIN 125-1 B B 8,4:56 ↔ ISO 4762 M8 x 20:4
- Passend:256 [Mate]: SUB-279310:1 ↔ DIN 125-1 B B 8,4:59
- Passend:258 [Mate]: SUB-279310:1 ↔ DIN 125-1 B B 8,4:60
- Passend:260 [Mate]: SUB-239310:1 ↔ DIN 125-1 B B 8,4:61
- Passend:262 [Mate]: SUB-239310:1 ↔ DIN 125-1 B B 8,4:62
- Passend:264 [Mate]: DIN 125-1 B B 8,4:61 ↔ ISO 4762 M8 x 16:47
- Passend:266 [Mate]: DIN 125-1 B B 8,4:61 ↔ ISO 4762 M8 x 16:48
- Passend:268 [Mate]: DIN 125-1 B B 8,4:60 ↔ ISO 4762 M8 x 16:49
- Passend:270 [Mate]: DIN 125-1 B B 8,4:60 ↔ ISO 4762 M8 x 16:50
- Passend:271 [Mate]: SUB-279310:1 ↔ SUB-299310:1
- Fluchtend:10 [Flush]: 500586R:1 ↔ SUB-299310:1
- Passend:272 [Mate]: 500586R:1 ↔ SUB-299310:1
- Passend:274 [Mate]: SUB-299310:1 ↔ DIN 125-1 B B 8,4:63
- Passend:276 [Mate]: SUB-299310:1 ↔ DIN 125-1 B B 8,4:64
- Passend:278 [Mate]: SUB-299310:1 ↔ DIN 125-1 B B 8,4:65
- Passend:280 [Mate]: SUB-299310:1 ↔ DIN 125-1 B B 8,4:66
- Passend:282 [Mate]: SUB-299310:1 ↔ DIN 125-1 B B 8,4:67
- Passend:284 [Mate]: SUB-299310:1 ↔ DIN 125-1 B B 8,4:68
- Passend:286 [Mate]: DIN 125-1 B B 8,4:67 ↔ ISO 4762 M8 x 20:5
- Passend:288 [Mate]: DIN 125-1 B B 8,4:67 ↔ ISO 4762 M8 x 20:6
- Passend:289 [Mate]: 500586R:1 ↔ SUB-269310:1
- Fluchtend:292 [Flush]: SUB-269310:1
- Passend:290 [Mate]: 500586R:1 ↔ SUB-269310:1
- Passend:292 [Mate]: SUB-269310:1 ↔ DIN 125-1 B B 8,4:75
- Passend:294 [Mate]: SUB-269310:1 ↔ DIN 125-1 B B 8,4:76
- Passend:295 [Mate]: 500586R:1 ↔ 500652R:1
- Fluchtend:293 [Flush]: 500586R:1 ↔ 500652R:1
- Passend:296 [Mate]: SUB-269310:1 ↔ 500652R:1
- Passend:297 [Mate]: 500586R:1 ↔ 500652L:1
- Passend:298 [Mate]: 500586R:1 ↔ 500652L:1
- Passend:299 [Mate]: SUB-269310:1 ↔ 500652L:1
- Fluchtend:294 [Flush]: SUB-259310:1
- Passend:390 [Mate]: 500586R:1 ↔ SUB-259310:1
- Fluchtend:295 [Flush]: 500586R:1 ↔ SUB-259310:1
- Fluchtend:391 [Flush]: 500586R:1 ↔ SUB-259310:1
- Passend:301 [Mate]: SUB-259310:1 ↔ DIN 125-1 B B 8,4:89
- Passend:303 [Mate]: SUB-259310:1 ↔ DIN 125-1 B B 8,4:90
- Passend:305 [Mate]: SUB-259310:1 ↔ DIN 125-1 B B 8,4:91
- Passend:307 [Mate]: SUB-259310:1 ↔ DIN 125-1 B B 8,4:92
- Passend:309 [Mate]: SUB-259310:1 ↔ DIN 125-1 B B 8,4:93
- Passend:311 [Mate]: SUB-259310:1 ↔ DIN 125-1 B B 8,4:94
- Passend:313 [Mate]: SUB-259310:1 ↔ DIN 125-1 B B 8,4:95
- Passend:315 [Mate]: SUB-259310:1 ↔ DIN 125-1 B B 8,4:96
- Passend:317 [Mate]: SUB-259310:1 ↔ DIN 125-1 B B 8,4:99
- Passend:319 [Mate]: SUB-259310:1 ↔ DIN 125-1 B B 8,4:100
- Passend:321 [Mate]: SUB-259310:1 ↔ DIN 125-1 B B 8,4:101
- Passend:323 [Mate]: SUB-259310:1 ↔ DIN 125-1 B B 8,4:102
- Passend:325 [Mate]: SUB-259310:1 ↔ DIN 125-1 B B 8,4:103
- Passend:327 [Mate]: SUB-259310:1 ↔ DIN 125-1 B B 8,4:104
- Passend:329 [Mate]: SUB-259310:1 ↔ DIN 125-1 B B 8,4:105
- Passend:331 [Mate]: SUB-259310:1 ↔ DIN 125-1 B B 8,4:106
- Passend:333 [Mate]: SUB-259310:1 ↔ DIN 125-1 B B 8,4:107
- Passend:335 [Mate]: SUB-259310:1 ↔ DIN 125-1 B B 8,4:108
- Passend:337 [Mate]: SUB-259310:1 ↔ DIN 125-1 B B 8,4:109
- Passend:339 [Mate]: SUB-259310:1 ↔ DIN 125-1 B B 8,4:110
- Passend:341 [Mate]: DIN 125-1 B B 8,4:110 ↔ ISO 4762 M8 x 20:11
- Passend:343 [Mate]: DIN 125-1 B B 8,4:110 ↔ ISO 4762 M8 x 20:12
- Passend:345 [Mate]: DIN 125-1 B B 8,4:110 ↔ ISO 4762 M8 x 20:13
- Passend:351 [Mate]: DIN 125-1 B B 8,4:110 ↔ ISO 4762 M8 x 20:16
- Passend:353 [Mate]: DIN 125-1 B B 8,4:100 ↔ ISO 4762 M8 x 20:17
- Passend:355 [Mate]: DIN 125-1 B B 8,4:100 ↔ ISO 4762 M8 x 20:18
- Passend:357 [Mate]: DIN 125-1 B B 8,4:100 ↔ ISO 4762 M8 x 20:19
- Passend:359 [Mate]: DIN 125-1 B B 8,4:100 ↔ ISO 4762 M8 x 20:20
- Passend:361 [Mate]: DIN 125-1 B B 8,4:89 ↔ ISO 4762 M8 x 20:21
- Passend:363 [Mate]: DIN 125-1 B B 8,4:89 ↔ ISO 4762 M8 x 20:22
- Passend:365 [Mate]: DIN 125-1 B B 8,4:89 ↔ ISO 4762 M8 x 20:23
- Passend:367 [Mate]: DIN 125-1 B B 8,4:89 ↔ ISO 4762 M8 x 20:24
- Passend:369 [Mate]: DIN 125-1 B B 8,4:93 ↔ ISO 4762 M8 x 16:51
- Passend:371 [Mate]: DIN 125-1 B B 8,4:93 ↔ ISO 4762 M8 x 16:52
- Passend:373 [Mate]: DIN 125-1 B B 8,4:93 ↔ ISO 4762 M8 x 16:53
- Passend:375 [Mate]: DIN 125-1 B B 8,4:93 ↔ ISO 4762 M8 x 16:54
- Passend:377 [Mate]: DIN 125-1 B B 8,4:85 ↔ ISO 4762 M8 x 16:55
- Passend:379 [Mate]: DIN 125-1 B B 8,4:85 ↔ ISO 4762 M8 x 16:56
- Fluchtend:389 [Flush]: SUB-279310:1 ↔ ADSK-014502:1
- Passend:381 [Mate]: SUB-279310:1 ↔ ADSK-014502:1
- Passend:382 [Mate]: SUB-279310:1 ↔ ADSK-014502:53
- Passend:383 [Mate]: SUB-279310:1 ↔ ADSK-014502:53
- Passend:384 [Mate]: ADSK-014502:52 ↔ ADSK-014502:53
- Fluchtend:298 [Flush]: SUB-239310:1 ↔ ADSK-014502:153
- Fluchtend:299 [Flush]: 500652L:1 ↔ ADSK-014502:153
- Passend:385 [Mate]: SUB-239310:1 ↔ ADSK-014502:153
- Passend:386 [Mate]: ADSK-014502:204 ↔ ADSK-014502:205
- Fluchtend:388 [Flush]: SUB-239310:1 ↔ ADSK-014502:205
- Passend:387 [Mate]: SUB-239310:1 ↔ ADSK-014502:205
- Fluchtend:390 [Flush]: 500652R:1 ↔ ADSK-014502:1
- Passend:388 [Mate]: SUB-239310:1 ↔ ADSK-014502:205
- Passend:389 [Mate]: ADSK-014502:204 ↔ ADSK-014502:205
- Fluchtend:392 [Flush]: SUB-279310:1 ↔ ADSK-014502:307
- Passend:391 [Mate]: ADSK-014389:1 ↔ ADSK-014502:307
- Fluchtend:393 [Flush]: ADSK-014389:1 ↔ ADSK-014502:307
